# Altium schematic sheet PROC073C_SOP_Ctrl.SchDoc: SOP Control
size 431 x 279 mm; Date: Not shown in title block; ApprovedBy: Not shown in title block; CheckedBy: Not shown in title block; Author: Not shown in title block; CompanyName: Not shown in title block; DrawnBy: Charles F. Oladimeji; Engineer: Not shown in title block; Organization: Not shown in title block; Address1: Not shown in title block; Address2: Not shown in title block; Address3: Not shown in title block; Address4: Not shown in title block; DocumentNumber: 11; Revision: Use project parameter SCH_Rev; SheetNumber: 11; SheetTotal: 13; PageSetup: Record=PageOptions¦CenterHorizontal=True¦CenterVertical=True¦PrintScale=1.00¦XCorrection=1.00¦YCorrection=1.00¦PrintKind=0¦BorderSize=5000000¦LeftOffset=0¦BottomOffset=0¦Orientation=2¦PaperLength=1000¦PaperWidth=1000¦Scale=100¦PaperSource=15¦PrintQuality=600¦MediaType=1¦DitherType=10¦PaperKind=Letter¦PrintScaleMode=1
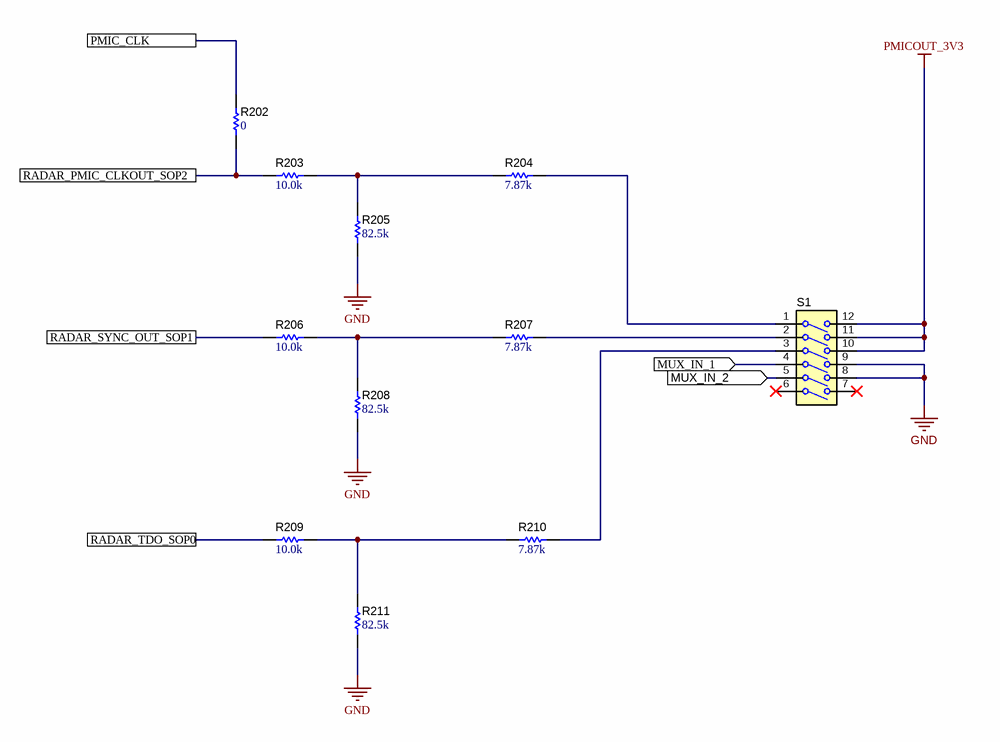
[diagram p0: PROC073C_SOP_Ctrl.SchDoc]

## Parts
R202  ValueDisplayed: 0  [0402L]  (hidden comment: ERJ-2GE0R00X)
R203  ValueDisplayed: 10.0k  [0402L]  (hidden comment: CRCW040210K0FKED)
R204  ValueDisplayed: 7.87k  [0402L]  (hidden comment: CRCW04027K87FKED)
R205  ValueDisplayed: 82.5k  [0402L]  (hidden comment: CRCW040282K5FKED)
R206  ValueDisplayed: 10.0k  [0402L]  (hidden comment: CRCW040210K0FKED)
R207  ValueDisplayed: 7.87k  [0402L]  (hidden comment: CRCW04027K87FKED)
R208  ValueDisplayed: 82.5k  [0402L]  (hidden comment: CRCW040282K5FKED)
R209  ValueDisplayed: 10.0k  [0402L]  (hidden comment: CRCW040210K0FKED)
R210  ValueDisplayed: 7.87k  [0402L]  (hidden comment: CRCW04027K87FKED)
R211  ValueDisplayed: 82.5k  [0402L]  (hidden comment: CRCW040282K5FKED)
S1  218-6LPST  [SW_218-6LPST]  (value not drawn)

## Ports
MUX_IN_1 (in), MUX_IN_2 (in), PMIC_CLK, RADAR_PMIC_CLKOUT_SOP2, RADAR_SYNC_OUT_SOP1, RADAR_TDO_SOP0

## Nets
GND: R205.1 R208.1 R211.1 S1.8(5A) S1.9(4A)
PMICOUT_3V3: S1.10(3A) S1.11(2A) S1.12(1A)
MUX_IN_1: S1.4 ; port MUX_IN_1
MUX_IN_2: S1.5 ; port MUX_IN_2
PMIC_CLK: R202.2 ; port PMIC_CLK
RADAR_PMIC_CLKOUT_SOP2: R202.1 R203.1 ; port RADAR_PMIC_CLKOUT_SOP2
RADAR_SYNC_OUT_SOP1: R206.1 ; port RADAR_SYNC_OUT_SOP1
RADAR_TDO_SOP0: R209.1 ; port RADAR_TDO_SOP0
NetR203_2: R203.2 R204.1 R205.2
NetR204_2: R204.2 S1.1
NetR206_2: R206.2 R207.1 R208.2
NetR207_2: R207.2 S1.2
NetR209_2: R209.2 R210.1 R211.2
NetR210_2: R210.2 S1.3

Not connected (* = marked no-connect by the designer): S1 6* 7(6A)*

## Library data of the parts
R202 = CMP-0026992-3: RES, 0, 5%, 0.1 W, AEC-Q200 Grade 0, 0402; Manufacturer: Panasonic; Power_W: 100mW; TempCo: 600 ppm/C; Value_Code: 0000; Value: 0; EIA_Code: E24; SizeX_mm: 1; SizeY_mm: 0.5; SizeZ_mm: 0.6; Value2: 0.1W; AEC Qualified: Y; VDC_V: 50V; AEC Category: Q200; SizeAreaWB_mm2: 3
R203 R206 R209 = CMP-0025958-3: RES, 10.0 k, 1%, 0.063 W, AEC-Q200 Grade 0, 0402; Manufacturer: Vishay-Dale; Power_W: 63mW; TempCo: 100 ppm/C; Value_Code: 10k0; Value: 10.0k; EIA_Code: E96; Res_ohm: 10k; SizeX_mm: 1; SizeY_mm: 0.5; SizeZ_mm: 0.6; Value2: 0.063W; AEC Qualified: Y; VDC_V: 50V; AEC Category: Q200; AEC Grade: 0
R204 R207 R210 = CMP-0026557-2: RES, 7.87 k, 1%, 0.063 W, AEC-Q200 Grade 0, 0402; Manufacturer: Vishay-Dale; Power_W: 63mW; TempCo: 100 ppm/C; Value_Code: 7k87; Value: 7.87k; EIA_Code: E96; SizeX_mm: 1; SizeY_mm: 0.5; SizeZ_mm: 0.6; Value2: 0.063W; AEC Qualified: Y; VDC_V: 50V; AEC Grade: 0; AEC Category: Q200
R205 R208 R211 = CMP-0026574-2: RES, 82.5 k, 1%, 0.063 W, AEC-Q200 Grade 0, 0402; Manufacturer: Vishay-Dale; Power_W: 63mW; TempCo: 100 ppm/C; Value_Code: 82k5; Value: 82.5k; EIA_Code: E96; SizeX_mm: 1; SizeY_mm: 0.5; SizeZ_mm: 0.6; Value2: 0.063W; AEC Qualified: Y; VDC_V: 50V; AEC Grade: 0; AEC Category: Q200
S1 = CMP-0002304-1: Switch, SPST, Slide, Off-On, 6 Pos, 0.025A, 24V, SMD; Manufacturer: CTS Electrocomponents; CurrentRating_mA: 25A; PositionCount: 6; SizeX_mm: 8.44; SizeY_mm: 8.79; SizeZ_mm: 2.65; SizeArea_mm2: 74.1876; SizeAreaWB_mm2: 112.6476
